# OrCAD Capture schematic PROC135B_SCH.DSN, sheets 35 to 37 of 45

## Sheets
35 35. USB1 TYPE-A: size C; title: SOC USB INTERFACE, USB1 TYPE A CONNECTOR, VBUS DIVIDER & POWER SWITCH
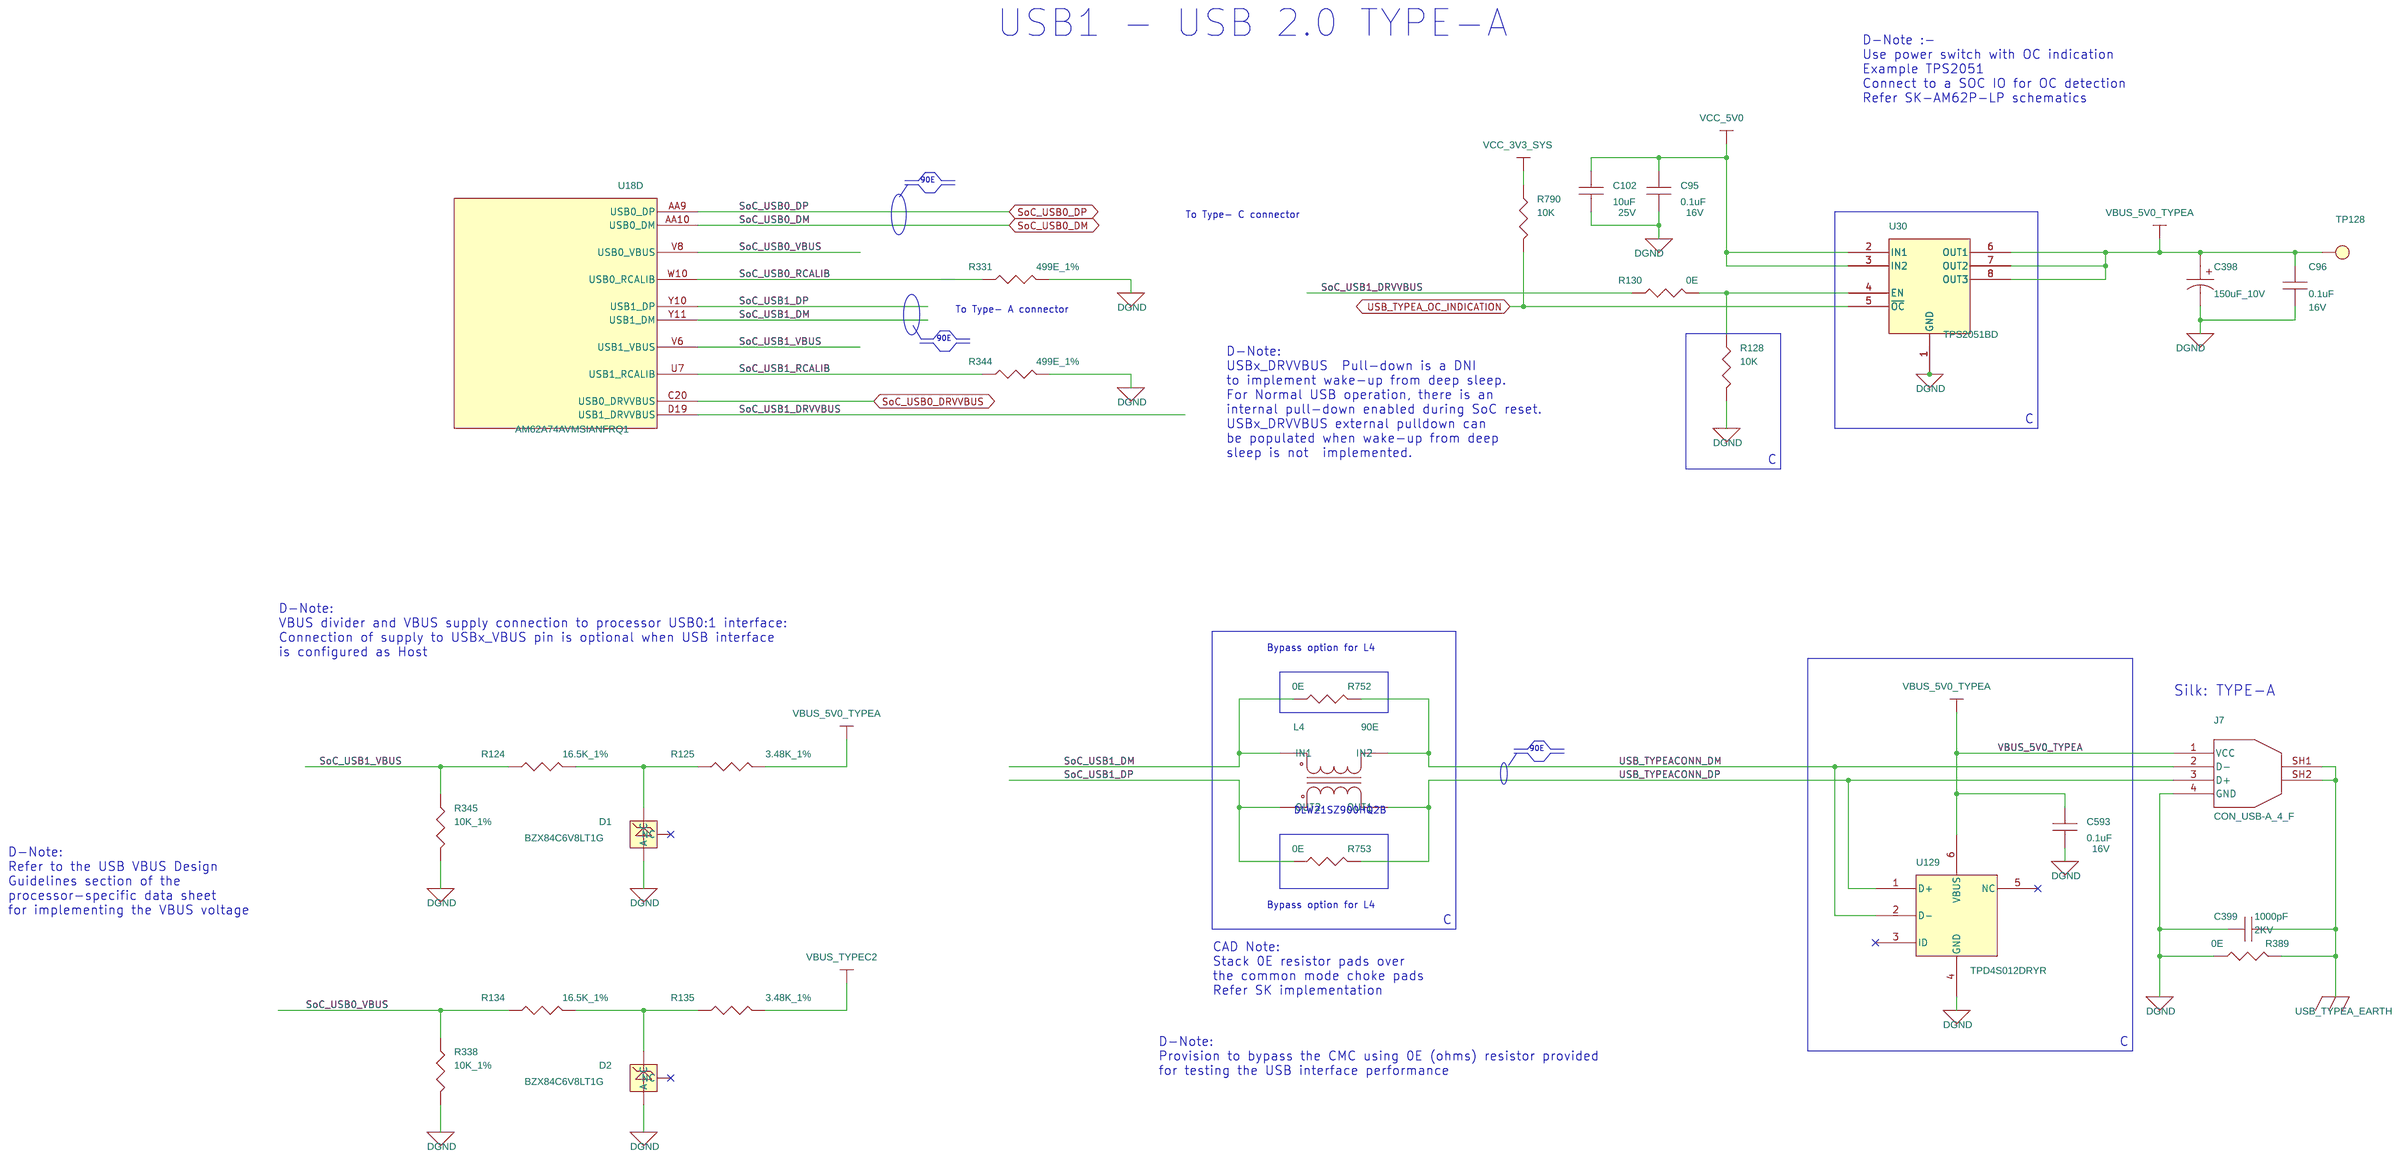
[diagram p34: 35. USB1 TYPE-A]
36 36. USB0 TYPE-C DRP & TEST LED: size C; title: USB0 TYPE-C DRP & USER TEST LEDS
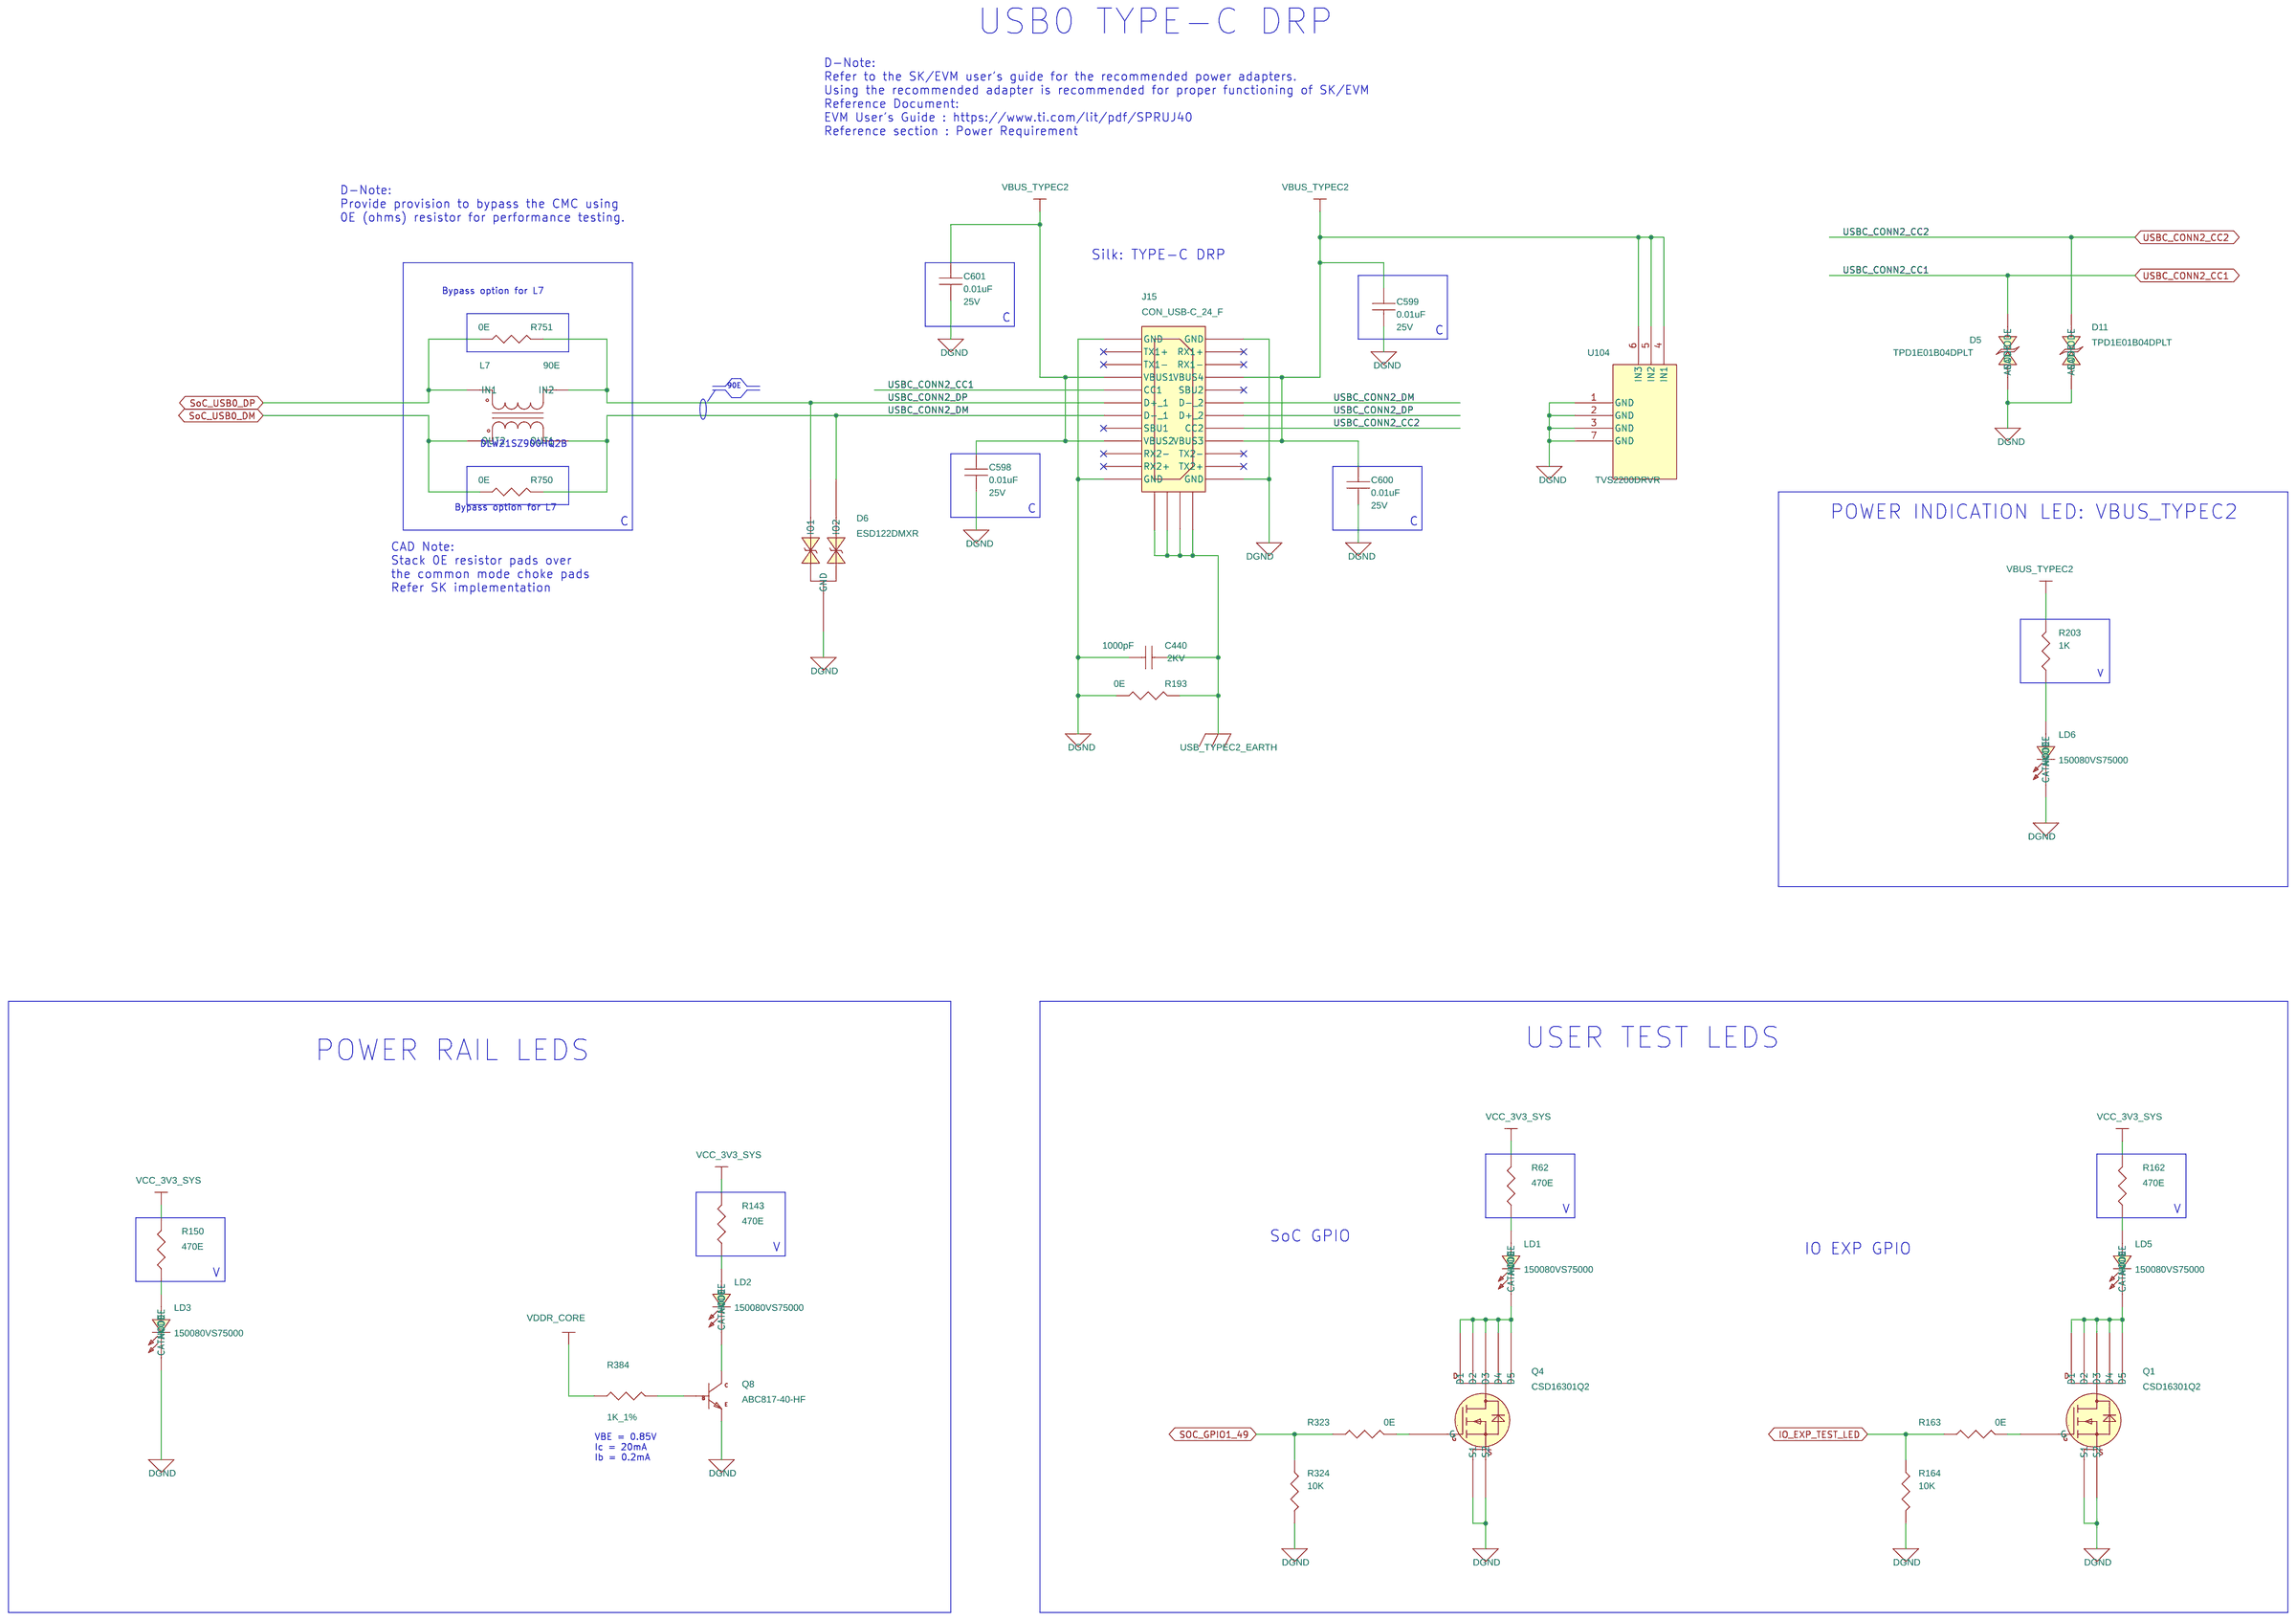
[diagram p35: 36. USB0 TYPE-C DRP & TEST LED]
37 37. SoC UART1 FET SWITCH & BUFF: size C; title: SoC UART1 FET SWITCH & BUFFER
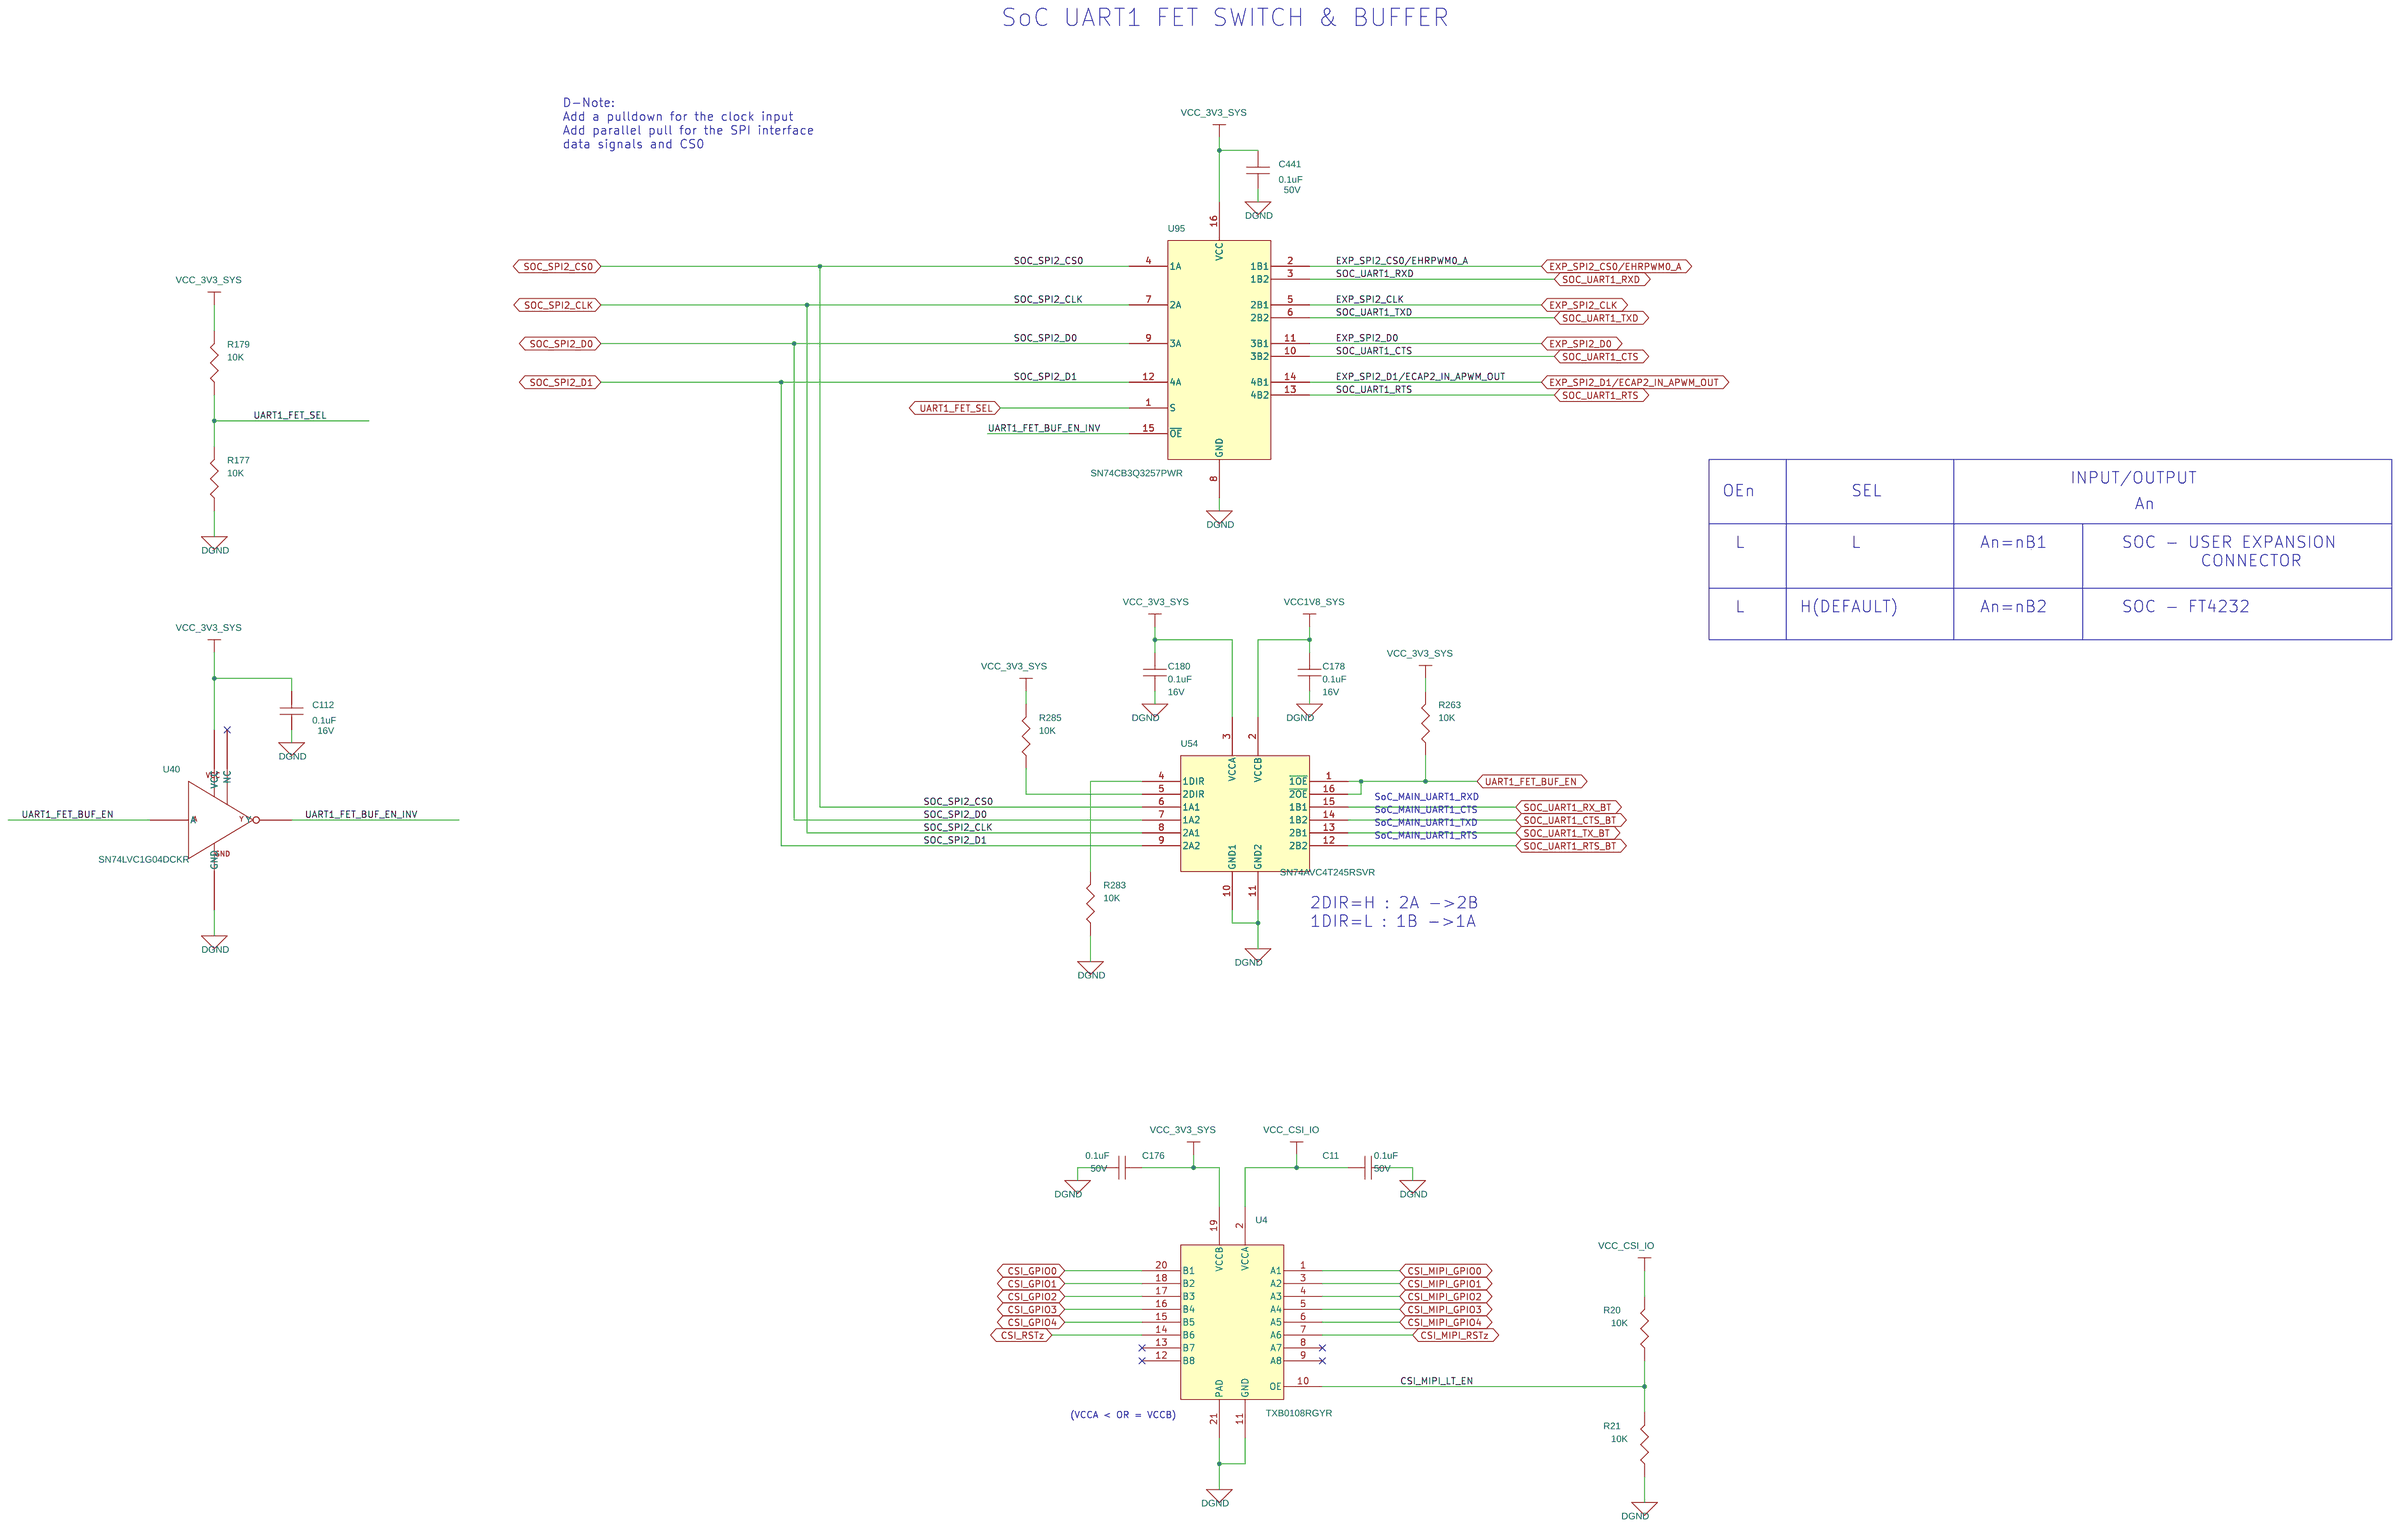
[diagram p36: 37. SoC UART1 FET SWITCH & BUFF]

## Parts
sheet 34. MCU HEADER
U18  AM62A74AVMSIANFRQ1  [FBGA484_31-49_710X710_2-7]  (sections A,B,C,D,E,F,G,H,I,J,K,L,M,N,O,P,Q)
sheet 35. USB1 TYPE-A
C95  0.1uF  [CAP0201_0-5]
C96  0.1uF  [CAP0201_0-5]
C102  10uF  [CAP0603_1]
C398  150uF_10V  [CAPT7343D_3-25]
C399  1000pF  [CAP1206_1-75]
C593  0.1uF  [CAP0201_0-5]
D1  BZX84C6V8LT1G  [SOT23-123_1-2]
D2  BZX84C6V8LT1G  [SOT23-123_1-2]
J7  CON_USB-A_4_F  [CON_USBA4_629104151_S_R_S_7-4]
L4  90E  [IND4_DLW21H_90X60_SMD_1-4]
R124  16.5K_1%  [RES0402_0-5]
R125  3.48K_1%  [RES0201_0-5]
R128  10K  [RES0201_0-5]
R130  0E  [RES0201_0-5]
R134  16.5K_1%  [RES0402_0-5]
R135  3.48K_1%  [RES0201_0-5]
R331  499E_1%  [RES0402_0-5]
R338  10K_1%  [RES0201_0-5]
R344  499E_1%  [RES0402_0-5]
R345  10K_1%  [RES0201_0-5]
R389  0E  [RES0603_0-75]
R752  0E  [RES0402_0-5]
R753  0E  [RES0402_0-5]
R790  10K  [RES0201_0-5]
TP128  TP20_SMD  [TP20_SMD]
U30  TPS2051BD  [SOIC8_1-8]
U129  TPD4S012DRYR  [SON6_SN74LVC2G17_40X60_0-6]
sheet 36. USB0 TYPE-C DRP & TEST LED
C440  1000pF  [CAP1206_1-75]
C598  0.01uF  [CAP0201_0-5]
C599  0.01uF  [CAP0201_0-5]
C600  0.01uF  [CAP0201_0-5]
C601  0.01uF  [CAP0201_0-5]
D5  TPD1E01B04DPLT  [DIO_DFN0201_0-4]
D6  ESD122DMXR  [X2SON3_ESD122DMX_30X40_0-4]
D11  TPD1E01B04DPLT  [DIO_DFN0201_0-4]
J15  CON_USB-C_24_F  [CON_USBC24_2012670_S_R_S_3-9]
L7  90E  [IND4_DLW21H_90X60_SMD_1-4]
LD1  150080VS75000  [LED_150080VS75000_80X50_SMD_0-8]
LD2  150080VS75000  [LED_150080VS75000_80X50_SMD_0-8]
LD3  150080VS75000  [LED_150080VS75000_80X50_SMD_0-8]
LD5  150080VS75000  [LED_150080VS75000_80X50_SMD_0-8]
LD6  150080VS75000  [LED_150080VS75000_80X50_SMD_0-8]
Q1  CSD16301Q2  [WSON6_CSD13202Q2_80X80_0-8]
Q4  CSD16301Q2  [WSON6_CSD13202Q2_80X80_0-8]
Q8  ABC817-40-HF  [SOT23-123_1-2]
R62  470E  [RES0402_0-5]
R143  470E  [RES0402_0-5]
R150  470E  [RES0402_0-5]
R162  470E  [RES0402_0-5]
R163  0E  [RES0402_0-5]
R164  10K  [RES0201_0-5]
R193  0E  [RES0603_0-75]
R203  1K  [RES0402_0-5]
R323  0E  [RES0402_0-5]
R324  10K  [RES0201_0-5]
R384  1K_1%  [RES0402_0-5]
R750  0E  [RES0402_0-5]
R751  0E  [RES0402_0-5]
U104  TVS2200DRVR  [SON6_25-59_85X85_0-8]
sheet 37. SoC UART1 FET SWITCH & BUFF
C11  0.1uF  [CAP0402_0-75]
C112  0.1uF  [CAP0201_0-5]
C176  0.1uF  [CAP0402_0-75]
C178  0.1uF  [CAP0201_0-5]
C180  0.1uF  [CAP0201_0-5]
C441  0.1uF  [CAP0402_0-75]
R20  10K  [RES0201_0-5]
R21  10K  [RES0201_0-5]
R177  10K  [RES0201_0-5]
R179  10K  [RES0201_0-5]
R263  10K  [RES0201_0-5]
R283  10K  [RES0201_0-5]
R285  10K  [RES0201_0-5]
U4  TXB0108RGYR  [QFN20_19-68_185X145_1]
U40  SN74LVC1G04DCKR  [SC70-5]
U54  SN74AVC4T245RSVR  [UQFN16_TMUX1574_70X100_0-6]
U95  SN74CB3Q3257PWR  [TSSOP16_25-59_205X180]

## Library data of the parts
U18 = AM62A-EVM_SOC_FCBGA484: IC AM62A SK EVM SoC MICROPROCESSOR FCBGA484; Chkd/date: PRADEEP/120225; Crtd /date: SHANKARI/120225; Custom_Duty: 15%; Customs_HS_Code: 85369090; Distributor_name: NA; Distributor_part_number: NA; Footprint Path: Y:\MIS_DATABASE\Library\ALTIUM_TOOL\PCB_FOOTPRINTS\Altium_Footprint_Lib.PcbLib; Height: 2.65MM; Library Path: Y:\MIS_DATABASE\Library\ALTIUM_TOOL\SCHEMATICS_PARTS\MS_MICROPROCESSOR_Library.schlib; Library Ref: AM62A-EVM_SoC_FCBGA484; Mfr_name: TEXAS INSTRUMENTS; Mistral Part No: 141225020003-R; Package: FCBGA484; Part_type: ICS\DIGITAL\MICROPROCESSOR; Project: AM62A_SK_EVM; RoHS: NA; Temperature: NA; Tolerance: NA; Voltage: NA; Wattage: NA; Weight: NA; Datasheet: Y:\MIS_DATABASE\DATASHEETS\ICS\DIGITAL\MICROCONTROLLER\AM62A_SK_EVM.PDF
C95 C96 C593 = CAP: CAP CERAMIC 0.1uF 16V 10% X5R 0201; Chkd/date: PRADEEP/130623; Crtd /date: PRADEEP/130623; Custom_Duty: 15%; Customs_HS_Code: 85322990; Distributor_name: NA; Distributor_part_number: NA; Footprint Path: Y:\MIS_DATABASE\Library\ALTIUM_TOOL\PCB_FOOTPRINTS\Altium_Footprint_Lib.PcbLib; Height: 0.33MM; Library Path: Y:\MIS_DATABASE\Library\ALTIUM_TOOL\SCHEMATICS_PARTS\MS_DISCRETE_Library.schlib; Mfr_name: MURATA; Mfr_part_number: GRT033R61C104KE01; Mistral Part No: 120022060019-R; Package: 0201; Part_type: CAPACITORS\CERAMIC; Project: AM62P_SK; RoHS: RoHS; Temperature: -55°C+85°C; Tolerance: 10%; Voltage: 16V; Wattage: NA; Weight: 0.33mg; Datasheet: Y:\MIS_DATABASE\DATASHEETS\CAPACITORS\GRT033R61C104KE01XX.PDF
C102 = CAP: CAP CERAMIC 10uF 25V 20% X5R AUTO 0603; Chkd/date: PRADEEP/130623; Crtd /date: PRADEEP/130623; Custom_Duty: 15%; Customs_HS_Code: 85322990; Distributor_name: NA; Distributor_part_number: NA; Footprint Path: Y:\MIS_DATABASE\Library\ALTIUM_TOOL\PCB_FOOTPRINTS\Altium_Footprint_Lib.PcbLib; Height: 1.00MM; Library Path: Y:\MIS_DATABASE\Library\ALTIUM_TOOL\SCHEMATICS_PARTS\MS_DISCRETE_Library.schlib; Mfr_name: MURATA; Mfr_part_number: GRT188R61E106ME13; Mistral Part No: 120022060023-R; Package: 0603; Part_type: CAPACITORS\CERAMIC; Project: AM62P_SK; RoHS: RoHS; Temperature: -55°C+85°C; Tolerance: 20%; Voltage: 25V; Wattage: NA; Weight: 2mg; Datasheet: Y:\MIS_DATABASE\DATASHEETS\CAPACITORS\GRT188R61E106ME13.PDF
C398 = CAP_POL: CAP TANTALUM 150uF 10V 10% ESR 600mE D7343; Chkd/date: ALVY/200921; Crtd /date: MANIRAJA/200921; Custom_Duty: 15%; Customs_HS_Code: 85322990; Distributor_name: DIGIKEY; Distributor_part_number: 718-1960-1-ND; Footprint Path: Y:\MIS_DATABASE\Library\ALTIUM_TOOL\PCB_FOOTPRINTS\Altium_Footprint_Lib.PcbLib; Height: 3.10MM; Library Path: Y:\MIS_DATABASE\Library\ALTIUM_TOOL\SCHEMATICS_PARTS\MS_DISCRETE_Library.schlib; Mfr_name: VISHAY; Mfr_part_number: 293D157X9010D2TE3; Mistral Part No: 120021090007-R; Package: D7343; Part_type: CAPACITORS\TANTALUM; Project: TI_AM62x SKEVM_BRD; RoHS: RoHS; Temperature: -55°C+125°C; Tolerance: 10%; Voltage: 10V; Wattage: NA; Weight: 400mg; Datasheet: Y:\MIS_DATABASE\DATASHEETS\CAPACITORS\293D_SER_MAR20.PDF
C399 C440 = CAP: CAP CERAMIC 1000pF 2KV 10% X7R 1206; Chkd/date: SHREESHAIL/291106; Crtd /date: MAZHAR/281106; Custom_Duty: 15%; Customs_HS_Code: 85322990; Distributor_name: DIGIKEY; Distributor_part_number: 478-2956-1-ND; Footprint Path: Y:\MIS_DATABASE\Library\ALTIUM_TOOL\PCB_FOOTPRINTS\Altium_Footprint_Lib.PcbLib; Height: 1.52MM; Library Path: Y:\MIS_DATABASE\Library\ALTIUM_TOOL\SCHEMATICS_PARTS\MS_DISCRETE_Library.schlib; Mfr_name: AVX CORPORATION; Mfr_part_number: 1206GC102KAT1A; Mistral Part No: 120015080006-R; Package: 1206; Part_type: CAPACITORS\CERAMIC; Project: ADR1B; RoHS: RoHS; Temperature: -55°C+125°C; Tolerance: 10%; Voltage: 2KV; Wattage: NA; Weight: 16.2mg; Datasheet: Y:\MIS_DATABASE\DATASHEETS\CAPACITORS\AVX_HV-MLC.PDF
D1 D2 = DIODE_ZENER_SOT23_13: DIODE ZENER 250mW 6.8V SOT23-123; Chkd/date: MANIRAJA/031017; Crtd /date: MANIRAJA/031017; Custom_Duty: 15%; Customs_HS_Code: 85412900; Distributor_name: DIGIKEY; Distributor_part_number: BZX84C6V8LT1GOSCT-ND; Height: 1.11MM; Mfr_name: ON SEMICONDUCTOR; Mistral Part No: 130017100002-R; Package: SOT23-123; Part_type: DIODE\ZENER; Project: TI_MAXIE_CPB; RoHS: RoHS; Temperature: -65°C+150°C; Tolerance: NA; Voltage: 6.8V; Wattage: NA; Weight: 8mg; Datasheet: Y:\MIS_DATABASE\DATASHEETS\DISCRETES\DIODES\BZX84XX.PDF
J7 = CON_USB-A_4_2SH: CON USB-A TYPE 4POS FEMALE RT SMD; Chkd/date: MANIRAJA/271017; Crtd /date: MANIRAJA/271017; Custom_Duty: 24%; Customs_HS_Code: 85369090; Distributor_name: DIGIKEY; Distributor_part_number: 732-5969-1-ND; Height: 7.35MM; Manufacturer: WURTH ELECTRONICS; Mfr_name: WURTH ELECTRONICS; Mfr_part_number: 629104151021; Mistral Part No: 150017100042-R; Package: SMD; Part_type: CONNECTOR\USB; Project: TI_SVB_MAXWELL_SPM; RoHS: RoHS; Temperature: -40°C+85°C; Tolerance: NA; Voltage: NA; Wattage: NA; Weight: NA; Datasheet: Y:\MIS_DATABASE\DATASHEETS\CONNECTORS\629104151021.PDF
L4 L7 = INDUCTOR_DLW31S: IND COMMON MODE CHOKE 90E 280mA SMD; Chkd/date: MANIRAJA/270619; Crtd /date: MANIRAJA/270619; Custom_Duty: 24%; Customs_HS_Code: 85437099; Distributor_name: NA; Distributor_part_number: NA; Footprint Path: Y:\MIS_DATABASE\Library\ALTIUM_TOOL\PCB_FOOTPRINTS\Altium_Footprint_Lib.PcbLib; Height: 1.40MM; Library Path: Y:\MIS_DATABASE\Library\ALTIUM_TOOL\SCHEMATICS_PARTS\MS_DISCRETE_Library.schlib; Mfr_name: MURATA; Mfr_part_number: DLW21SZ900HQ2B; Mistral Part No: 130019060035-R; Package: SMD; Part_type: INDUCTOR; Project: TI_J7ES_CP; RoHS: RoHS; Temperature: -40°C+105°C; Tolerance: NA; Voltage: NA; Wattage: NA; Weight: 11mg; Datasheet: Y:\MIS_DATABASE\DATASHEETS\DISCRETES\INDUCTORS\DLW21SZ900HQ2B.PDF
R124 R134 = RESISTOR: RES 16.5K 1/16W 1% 0402; Chkd/date: ALVY/091220; Crtd /date: MANIRAJA/091220; Custom_Duty: 15%; Customs_HS_Code: 85332119; Distributor_name: DIGIKEY; Distributor_part_number: YAG3002CT-ND; Footprint Path: Y:\MIS_DATABASE\Library\ALTIUM_TOOL\PCB_FOOTPRINTS\Altium_Footprint_Lib.PcbLib; Height: 0.40MM; Library Path: Y:\MIS_DATABASE\Library\ALTIUM_TOOL\SCHEMATICS_PARTS\MS_DISCRETE_Library.schlib; Mfr_name: YAGEO AMERICA; Mfr_part_number: RC0402FR-0716K5L; Mistral Part No: 110020120011-R; Package: 0402; Part_type: RESISTORS\FIXED; Project: TI_AM243x LP EVM; RoHS: RoHS; Temperature: -55°C+155°C; Tolerance: 1%; Voltage: NA; Wattage: 1/16W; Weight: 0.65mg; Datasheet: Y:\MIS_DATABASE\DATASHEETS\RESISTORS\RCXXXXL-SER_MAR18.PDF
R125 R135 = RESISTOR: RES 3.48K 1/20W 1% 0201; Chkd/date: PRADEEP/281123; Crtd /date: TAMILARASU/071123; Custom_Duty: 15%; Customs_HS_Code: 85322990; Distributor_name: DIGIKEY; Distributor_part_number: P122951CT-ND; Footprint Path: Y:\MIS_DATABASE\Library\ALTIUM_TOOL\PCB_FOOTPRINTS\Altium_Footprint_Lib.PcbLib; Height: 0.26MM; Library Path: Y:\MIS_DATABASE\Library\ALTIUM_TOOL\SCHEMATICS_PARTS\MS_DISCRETE_Library.schlib; Mfr_name: PANASONIC-ECG; Mfr_part_number: ERJ-1GNF3481C; Mistral Part No: 110023110006-R; Package: 0201; Part_type: RESISTORS\FIXED; Project: AM62P SK; RoHS: RoHS; Temperature: -55°C+125°C; Tolerance: 0.01; Voltage: NA; Wattage: 1/20W; Weight: 0.15mg; Datasheet: Y:\MIS_DATABASE\DATASHEETS\RESISTORS\PAN-ERJSER_DEC22.PDF
R20 R21 R128 R164 R177 R179 R263 R283 R285 R324 R790 = RESISTOR: RES 10K 1/20W 5% 0201; Chkd/date: MANIRAJA/050517; Crtd /date: MANIRAJA/050517; Custom_Duty: 15%; Customs_HS_Code: 85332119; Distributor_name: DIGIKEY; Distributor_part_number: 311-10KNCT-ND; Footprint Path: Y:\MIS_DATABASE\Library\ALTIUM_TOOL\PCB_FOOTPRINTS\Altium_Footprint_Lib.PcbLib; Height: 0.26MM; Library Path: Y:\MIS_DATABASE\Library\ALTIUM_TOOL\SCHEMATICS_PARTS\MS_DISCRETE_Library.schlib; Mfr_name: YAGEO AMERICA; Mfr_part_number: RC0201JR-0710KL; Mistral Part No: 110010070051-R; Package: 0201; Part_type: RESISTORS\FIXED; Project: GOLDEN-I LITE; RoHS: RoHS; Temperature: -55°C+125°C; Tolerance: 5%; Voltage: NA; Wattage: 1/20W; Weight: 0.17mg; Datasheet: Y:\MIS_DATABASE\DATASHEETS\RESISTORS\RCXXXXL-SER_MAR18.PDF
R130 = RESISTOR: RES 0E 1/20W 5% 0201; Chkd/date: NAVEED/301214; Crtd /date: MUDDU/120710; Custom_Duty: 15%; Customs_HS_Code: 85332119; Distributor_name: DIGIKEY; Distributor_part_number: 311-0.0NCT-ND; Footprint Path: Y:\MIS_DATABASE\Library\ALTIUM_TOOL\PCB_FOOTPRINTS\Altium_Footprint_Lib.PcbLib; Height: 0.26MM; Library Path: Y:\MIS_DATABASE\Library\ALTIUM_TOOL\SCHEMATICS_PARTS\MS_DISCRETE_Library.schlib; Mfr_name: YAGEO AMERICA; Mfr_part_number: RC0201JR-070RL; Mistral Part No: 110010070067-R; Package: 0201; Part_type: RESISTORS\FIXED; Project: PB_BUGBASE; RoHS: RoHS; Temperature: -55°C+125°C; Tolerance: 5%; Voltage: NA; Wattage: 1/20W; Weight: 0.17mg; Datasheet: Y:\MIS_DATABASE\DATASHEETS\RESISTORS\RCXXXXL-SER_MAR18.PDF
R331 R344 = RESISTOR: RES 499E 1/16W 1% 0402; Chkd/date: MANIRAJA/051020; Crtd /date: ALVY/051020; Custom_Duty: 15%; Customs_HS_Code: 85332119; Distributor_name: DIGIKEY; Distributor_part_number: 311-499LRCT-ND; Footprint Path: Y:\MIS_DATABASE\Library\ALTIUM_TOOL\PCB_FOOTPRINTS\Altium_Footprint_Lib.PcbLib; Height: 0.40MM; Library Path: Y:\MIS_DATABASE\Library\ALTIUM_TOOL\SCHEMATICS_PARTS\MS_DISCRETE_Library.schlib; Mfr_name: YAGEO AMERICA; Mfr_part_number: RC0402FR-07499RL; Mistral Part No: 110020080006-R; Package: 0402; Part_type: RESISTORS\FIXED; Project: AM64XX_EVM; RoHS: RoHS; Temperature: -55°C+155°C; Tolerance: 1%; Voltage: NA; Wattage: 1/16W; Weight: 0.65mg; Datasheet: Y:\MIS_DATABASE\DATASHEETS\RESISTORS\RCXXXXL-SER_MAR18.PDF
R338 R345 = RESISTOR: RES 10K 1/20W 1% 0201; Chkd/date: VASANTHA/270117; Crtd /date: MANIRAJA/270117; Custom_Duty: 15%; Customs_HS_Code: 85332119; Distributor_name: DIGIKEY; Distributor_part_number: 311-10.0KMCT-ND; Footprint Path: Y:\MIS_DATABASE\Library\ALTIUM_TOOL\PCB_FOOTPRINTS\Altium_Footprint_Lib.PcbLib; Height: 0.26MM; Library Path: Y:\MIS_DATABASE\Library\ALTIUM_TOOL\SCHEMATICS_PARTS\MS_DISCRETE_Library.schlib; Mfr_name: YAGEO AMERICA; Mfr_part_number: RC0201FR-0710KL; Mistral Part No: 110011040018-R; Package: 0201; Part_type: RESISTORS\FIXED; Project: GOLDEN-I LITE; RoHS: RoHS; Temperature: -55°C+125°C; Tolerance: 1%; Voltage: NA; Wattage: 1/20W; Weight: 0.17mg; Datasheet: Y:\MIS_DATABASE\DATASHEETS\RESISTORS\RCXXXXL-SER_MAR18.PDF
R193 R389 = RESISTOR: RES 0E 1/10W 5% 0603; Chkd/date: MANIRAJA/051217; Crtd /date: BAVISH/180211; Custom_Duty: 15%; Customs_HS_Code: 85332119; Distributor_name: DIGIKEY; Distributor_part_number: 311-0.0GRCT-ND; Footprint Path: Y:\MIS_DATABASE\Library\ALTIUM_TOOL\PCB_FOOTPRINTS\Altium_Footprint_Lib.PcbLib; Height: 0.55MM; Library Path: Y:\MIS_DATABASE\Library\ALTIUM_TOOL\SCHEMATICS_PARTS\MS_DISCRETE_Library.schlib; Manufacturer: YAGEO AMERICA; Mfr_name: PANASONIC-ECG; Mfr_part_number: RC0603JR-070RL; Mistral Part No: 110011020013-R; Package: 0603; Part_type: RESISTORS\FIXED; Project: KENNEL; RoHS: RoHS; Temperature: -55°C+155°C; Tolerance: 5%; Voltage: NA; Wattage: 1/10W; Weight: 2mg; Datasheet: Y:\MIS_DATABASE\DATASHEETS\RESISTORS\RCXXXXL-SER_MAR18.PDF
R163 R323 R750-R753 = RESISTOR: RES 0E 1/16W JUMPER 0402; Chkd/date: VASANTHA/201216; Crtd /date: MUDDU/190810; Custom_Duty: 15%; Customs_HS_Code: 85332119; Distributor_name: DIGIKEY; Distributor_part_number: 541-0.0JCT-ND; Footprint Path: Y:\MIS_DATABASE\Library\ALTIUM_TOOL\PCB_FOOTPRINTS\Altium_Footprint_Lib.PcbLib; Height: 0.40MM; Library Path: Y:\MIS_DATABASE\Library\ALTIUM_TOOL\SCHEMATICS_PARTS\MS_DISCRETE_Library.schlib; Mfr_name: VISHAY; Mfr_part_number: CRCW04020000Z0ED; Mistral Part No: 110010080019-R; Package: 0402; Part_type: RESISTORS\FIXED; Project: PB_BUGBASE; RoHS: RoHS; Temperature: -55°C+155°C; Tolerance: NA; Voltage: NA; Wattage: 1/16W; Weight: 0.65mg; Datasheet: Y:\MIS_DATABASE\DATASHEETS\RESISTORS\CRCW0603.PDF
TP128 = TESTPOINT: TESTPOINT CIR 20 SMD; Chkd/date: SHREESHAIL/171006; Crtd /date: MAZHAR/171006; Custom_Duty: NA; Customs_HS_Code: NA; Distributor_name: NA; Distributor_part_number: NA; Footprint Path: Y:\MIS_DATABASE\Library\ALTIUM_TOOL\PCB_FOOTPRINTS\Altium_Footprint_Lib.PcbLib; Height: NA; Library Path: Y:\MIS_DATABASE\Library\ALTIUM_TOOL\SCHEMATICS_PARTS\MS_DISCRETE_Library.schlib; MECHANICAL 3D STEP FILE: NA; Mfr_name: LOCAL; Mistral Part No: NA; Package: SMD; Project: BT MODULE_CSRBC04; RoHS: NA; Temperature: NA; Tolerance: NA; Voltage: NA; Wattage: NA; Weight: NA; Datasheet: NA
U30 = TPS2051BD_SOIC8: IC POWER DISTRIBUTION SWITCH SOIC8; Chkd/date: NAVEED/150714; Crtd /date: VASANTHA/190614; Custom_Duty: 15%; Customs_HS_Code: 85423100; Distributor_name: DIGIKEY; Distributor_part_number: 296-26911-5-ND; Footprint Path: Y:\MIS_DATABASE\Library\ALTIUM_TOOL\PCB_FOOTPRINTS\Altium_Footprint_Lib.PcbLib; Height: 1.75MM; Library Path: Y:\MIS_DATABASE\Library\ALTIUM_TOOL\SCHEMATICS_PARTS\MS_MISCPOWER_Library.schlib; Mfr_name: TEXAS INSTRUMENTS; Mistral Part No: 142014060011-R; Package: SOIC8; Part_type: ICS\POWER; Project: AEGIS_POM; RoHS: RoHS; Temperature: -40°C+125°C; Tolerance: NA; Voltage: NA; Wattage: NA; Weight: 72.6mg; Datasheet: Y:\MIS_DATABASE\DATASHEETS\MISC\REGULATORS\TPS2051BDBVR.PDF
U129 = TPD4S012DRY_SON6: IC 4CH ESD SOLUTION FOR USB-HS/USB OTG/USB CHARGER INTERFACE SON6; Chkd/date: MANIRAJA/040719; Crtd /date: BAVISH/190811; Custom_Duty: 15%; Customs_HS_Code: 85423100; Distributor_name: DIGIKEY; Distributor_part_number: 296-24244-1-ND; Footprint Path: Y:\MIS_DATABASE\Library\ALTIUM_TOOL\PCB_FOOTPRINTS\Altium_Footprint_Lib.PcbLib; Height: 0.60MM; Library Path: Y:\MIS_DATABASE\Library\ALTIUM_TOOL\SCHEMATICS_PARTS\MS_MISCINTERFACE_Library.schlib; Mfr_name: TEXAS INSTRUMENTS; Mistral Part No: 141011080022-R; Package: SON6; Part_type: ICS\INTERFACE; Project: ACRO_DM3730; RoHS: RoHS; Temperature: -40°C+85°C; Tolerance: NA; Voltage: NA; Wattage: NA; Weight: 3.2mg; Datasheet: Y:\MIS_DATABASE\DATASHEETS\ICS\INTERFACE\TPD4S012DRYR.PDF
C598-C601 = CAP: CAP CERAMIC 0.01uF 25V 10% X5R AUTO 0201; Chkd/date: MANIRAJA/311221; Crtd /date: ALVY/301221; Custom_Duty: 15%; Customs_HS_Code: 85322990; Distributor_name: MOUSER; Distributor_part_number: 81-GRT033R61E103KE1D; Footprint Path: Y:\MIS_DATABASE\Library\ALTIUM_TOOL\PCB_FOOTPRINTS\Altium_Footprint_Lib.PcbLib; Height: 0.33MM; Library Path: Y:\MIS_DATABASE\Library\ALTIUM_TOOL\SCHEMATICS_PARTS\MS_DISCRETE_Library.schlib; Mfr_name: MURATA; Mfr_part_number: GRT033R61E103KE01D; Mistral Part No: 120021120019-R; Package: 0201; Part_type: CAPACITORS\CERAMIC; Project: AM62Q_SKEVM_BRD; RoHS: RoHS; Temperature: -55°C+85°C; Tolerance: 10%; Voltage: 25V; Wattage: NA; Weight: 0.33mg; Datasheet: Y:\MIS_DATABASE\DATASHEETS\CAPACITORS\GRT033R61E103KE01.PDF
D5 D11 = DIODE_TVS_DUAL: DIODE 1CH ESD PROTECTION FOR USB TYPE-C AND THUNDERBOLT3 X2SON2; Chkd/date: MANIRAJA/230920; Crtd /date: ALVY/230920; Custom_Duty: 15%; Customs_HS_Code: 85412900; Distributor_name: DIGIKEY; Distributor_part_number: 296-44484-1-ND; Footprint Path: Y:\MIS_DATABASE\Library\ALTIUM_TOOL\PCB_FOOTPRINTS\Altium_Footprint_Lib.PcbLib; Height: 0.32MM; Library Path: Y:\MIS_DATABASE\Library\ALTIUM_TOOL\SCHEMATICS_PARTS\MS_DISCRETE_Library.schlib; Mfr_name: TEXAS INSTRUMENTS; Mistral Part No: 130020090037-R; Package: X2SON2; Part_type: DIODE\TVS; Project: AM64X_SKEVM; RoHS: RoHS; Temperature: -40°C+125°C; Tolerance: NA; Voltage: NA; Wattage: NA; Weight: 0.2mg; Datasheet: Y:\MIS_DATABASE\DATASHEETS\DISCRETES\DIODES\TPD1E01B04.PDF
D6 = DIODE_ESD122DMXR: DIODE 2-CH ESD PROTECTION FOR USB TYPE-C AND HDMI 2.0 X2SON-3; Chkd/date: MANIRAJA/140817; Crtd /date: MANIRAJA/140817; Custom_Duty: 15%; Customs_HS_Code: 85412900; Distributor_name: DIGIKEY; Distributor_part_number: ESD122DMXR-ND; Height: 0.40MM; Mfr_name: TEXAS INSTRUMENTS; Mistral Part No: 130017080015-R; Package: X2SON-3; Part_type: DIODE\TVS; Project: TI_SVB_CONTROLLER CARD; RoHS: RoHS; Temperature: -40°C+125°C; Tolerance: NA; Voltage: NA; Wattage: NA; Weight: NA; Datasheet: Y:\MIS_DATABASE\DATASHEETS\DISCRETES\DIODES\ESD122XX.PDF
J15 = CON_USB-C_24_1240183621: CON USB-C TYPE 24POS FEMALE RT SMD; Chkd/date: MANIRAJA/050618; Crtd /date: ALVY/040618; Custom_Duty: 24%; Customs_HS_Code: 85369090; Distributor_name: DIGIKEY; Distributor_part_number: WM17992CT-ND; Footprint Path: Y:\MIS_DATABASE\Library\ALTIUM_TOOL\PCB_FOOTPRINTS\Altium_Footprint_Lib.PcbLib; Height: 3.86MM; Library Path: Y:\MIS_DATABASE\Library\ALTIUM_TOOL\SCHEMATICS_PARTS\MS_CONNECTOR_Library.schlib; Mfr_name: MOLEX; Mfr_part_number: 2012670005; Mistral Part No: 150018060002-R; Package: SMD; Part_type: CONNECTOR\USB; Project: TI_J7SVB_USB_ADD-ON-CARD; RoHS: RoHS; Temperature: -40°C+105°C; Tolerance: NA; Voltage: NA; Wattage: NA; Weight: 0.686g; Datasheet: Y:\MIS_DATABASE\DATASHEETS\CONNECTORS\2012670X.PDF
LD1-LD3 LD5 LD6 = DIODE_LED: DIODE LED BRIGHT GREEN SMD; Chkd/date: MANIRAJA/180820; Crtd /date: ALVY/180820; Custom_Duty: 24%; Customs_HS_Code: 85439000; Distributor_name: DIGIKEY; Distributor_part_number: 732-4986-1-ND; Footprint Path: Y:\MIS_DATABASE\Library\ALTIUM_TOOL\PCB_FOOTPRINTS\Altium_Footprint_Lib.PcbLib; Height: 0.80MM; Library Path: Y:\MIS_DATABASE\Library\ALTIUM_TOOL\SCHEMATICS_PARTS\MS_OPTO_Library.schlib; Mfr_name: WURTH ELECTRONICS; Mistral Part No: 130020080012-R; Package: SMD; Part_type: OPTO\LED; Project: AM64x_EVM_BRD; RoHS: RoHS; Temperature: -40°C+85°C; Tolerance: NA; Voltage: NA; Wattage: NA; Weight: 10mg; Datasheet: Y:\MIS_DATABASE\DATASHEETS\DISCRETES\LEDS\150080VS75000.PDF
Q1 Q4 = MOSFET_CSD17313Q2: IC MOSFET N-CHANNEL NEXFET 25V WSON6; Chkd/date: ALVY/071220; Crtd /date: MANIRAJA/071220; Custom_Duty: 15%; Customs_HS_Code: 85423100; Distributor_name: DIGIKEY; Distributor_part_number: 296-25260-1-ND; Footprint Path: Y:\MIS_DATABASE\Library\ALTIUM_TOOL\PCB_FOOTPRINTS\Altium_Footprint_Lib.PcbLib; Height: 0.80MM; Library Path: Y:\MIS_DATABASE\Library\ALTIUM_TOOL\SCHEMATICS_PARTS\MS_MOSFET_Library.schlib; Manufacturer: TEXAS INSTRUMENTS; Mfr_name: TEXAS INSTRUMENTS; Mistral Part No: 142020120008-R; Package: WSON6; Part_type: ICS\POWER\MOSFET; Project: TI_AM243x LP EVM; RoHS: RoHS; Temperature: -55°C+150°C; Tolerance: NA; Voltage: NA; Wattage: NA; Weight: 8.7mg; Datasheet: Y:\MIS_DATABASE\DATASHEETS\ICS\POWER\CSD16301Q2.PDF
Q8 = NPN_123_SOT23-3: TRANSISTOR 45V 500mA NPN GENERAL PURPOSE SOT23-3; Chkd/date: PRAVEEN/260822; Crtd /date: PRAVEEN/260822; Custom_Duty: 15%; Customs_HS_Code: 85423100; Distributor_name: MOUSER; Distributor_part_number: 750-ABC817-40-HF; Footprint Path: Y:\MIS_DATABASE\Library\ALTIUM_TOOL\PCB_FOOTPRINTS\Altium_Footprint_Lib.PcbLib; Height: 1.20MM; Library Path: Y:\MIS_DATABASE\Library\ALTIUM_TOOL\SCHEMATICS_PARTS\MS_MOSFET_Library.schlib; Mfr_name: COMCHIP; Mistral Part No: 142022080040-R; Package: TO-252-3; Part_type: TRANSISTOR\BJT; Project: MS_TI_TMDS64SKEVM; RoHS: RoHS; Temperature: -55°C+150°C; Tolerance: NA; Voltage: 45V; Wattage: NA; Weight: NA; Datasheet: Y:\MIS_DATABASE\DATASHEETS\DISCRETES\TRANSISTORS_FETS\ABC817-40-HF.PDF
R62 R143 R150 R162 = RESISTOR: RES 470E 1/10W 5% 0402; Chkd/date: SHREESHAIL/24050; Crtd /date: MAZHAR/260706; Custom_Duty: 15%; Customs_HS_Code: 85332119; Distributor_name: DIGIKEY; Distributor_part_number: P470JCT-ND; Footprint Path: Y:\MIS_DATABASE\Library\ALTIUM_TOOL\PCB_FOOTPRINTS\Altium_Footprint_Lib.PcbLib; Height: 0.40MM; Library Path: Y:\MIS_DATABASE\Library\ALTIUM_TOOL\SCHEMATICS_PARTS\MS_DISCRETE_Library.schlib; Mfr_name: PANASONIC-ECG; Mfr_part_number: ERJ-2GEJ471X; Mistral Part No: 110009030859-R; Package: 0402; Part_type: RESISTORS\FIXED; Project: POWERBOX; RoHS: RoHS; Temperature: -55°C+155°C; Tolerance: 5%; Voltage: NA; Wattage: 1/10W; Weight: 0.8mg; Datasheet: Y:\MIS_DATABASE\DATASHEETS\RESISTORS\PAN-ERJSER_NOV17.PDF
R203 = RESISTOR: RES 1K 1/10W 5% 0402; Chkd/date: VASANTHA/201216; Crtd /date: MAZHAR/230805; Custom_Duty: 15%; Customs_HS_Code: 85332119; Distributor_name: DIGIKEY; Distributor_part_number: P1.0KJCT-ND; Footprint Path: Y:\MIS_DATABASE\Library\ALTIUM_TOOL\PCB_FOOTPRINTS\Altium_Footprint_Lib.PcbLib; Height: 0.40MM; Library Path: Y:\MIS_DATABASE\Library\ALTIUM_TOOL\SCHEMATICS_PARTS\MS_DISCRETE_Library.schlib; Mfr_name: PANASONIC-ECG; Mfr_part_number: ERJ-2GEJ102X; Mistral Part No: 110009030400-R; Package: 0402; Part_type: RESISTORS\FIXED; Project: HSE; RoHS: RoHS; Temperature: -55°C+155°C; Tolerance: 5%; Voltage: NA; Wattage: 1/10W; Weight: 0.8mg; Datasheet: Y:\MIS_DATABASE\DATASHEETS\RESISTORS\PAN-ERJSER_NOV17.PDF
R384 = RESISTOR: RES 1K 1/10W 1% 0402; Chkd/date: VASANTHA/281216; Crtd /date: MAZHAR/150506; Custom_Duty: 15%; Customs_HS_Code: 85332119; Distributor_name: DIGIKEY; Distributor_part_number: P1.00KLCT-ND; Footprint Path: Y:\MIS_DATABASE\Library\ALTIUM_TOOL\PCB_FOOTPRINTS\Altium_Footprint_Lib.PcbLib; Height: 0.40MM; Library Path: Y:\MIS_DATABASE\Library\ALTIUM_TOOL\SCHEMATICS_PARTS\MS_DISCRETE_Library.schlib; Mfr_name: PANASONIC-ECG; Mfr_part_number: ERJ-2RKF1001X; Mistral Part No: 110009030411-R; Package: 0402; Part_type: RESISTORS\FIXED; Project: VOCERA; RoHS: RoHS; Temperature: -55°C+155°C; Tolerance: 1%; Voltage: NA; Wattage: 1/10W; Weight: 0.8mg; Datasheet: Y:\MIS_DATABASE\DATASHEETS\RESISTORS\PAN-ERJSER_NOV17.PDF
U104 = TVS2200_WSON6: IC 22V FLAT-CLAMP SURGE PROTECTION DEVICE WSON6; Chkd/date: MANIRAJA/011021; Crtd /date: ALVY/011021; Custom_Duty: 15%; Customs_HS_Code: 85423100; Distributor_name: DIGIKEY; Distributor_part_number: 296-52187-1-ND; Footprint Path: Y:\MIS_DATABASE\Library\ALTIUM_TOOL\PCB_FOOTPRINTS\Altium_Footprint_Lib.PcbLib; Height: 0.80MM; Library Path: Y:\MIS_DATABASE\Library\ALTIUM_TOOL\SCHEMATICS_PARTS\MS_MISCPOWER_Library.schlib; Mfr_name: TEXAS INSTRUMENTS; Mistral Part No: 142021100001-R; Package: WSON6; Part_type: ICS\POWER; Project: TI_AM62x SKEVM_BRD; RoHS: RoHS; Temperature: -40°C+125°C; Tolerance: NA; Voltage: NA; Wattage: NA; Weight: 12mg; Datasheet: Y:\MIS_DATABASE\DATASHEETS\ICS\POWER\TVS2200.PDF
C11 C176 C441 = CAP: CAP CERAMIC 0.1uF 50V 10% X7R AUTO 0402; Alt_Mfr_name: YAGEO AMERICA; Alt_Mfr_part_number: CC0402KRX5R8BB104; Chkd/date: MANIRAJA/250221; Crtd /date: ALVY/240221; Custom_Duty: 15%; Customs_HS_Code: 85322990; Distributor_name: MOUSER; Distributor_part_number: 81-GRT155R71H104KE1D; Footprint Path: Y:\MIS_DATABASE\Library\ALTIUM_TOOL\PCB_FOOTPRINTS\Altium_Footprint_Lib.PcbLib; Height: 0.55MM; Library Path: Y:\MIS_DATABASE\Library\ALTIUM_TOOL\SCHEMATICS_PARTS\MS_DISCRETE_Library.schlib; Mfr_name: MURATA; Mfr_part_number: GRT155R71H104KE01D; Mistral Part No: 120019030005-R; Package: 0402; Part_type: CAPACITORS\CERAMIC; Project: TI_DRA821 SK EVM BRD; RoHS: RoHS; Temperature: -55°C+125°C; Tolerance: 10%; Voltage: 50V; Wattage: NA; Weight: NA; Datasheet: Y:\MIS_DATABASE\DATASHEETS\CAPACITORS\GRT155R71H104KE01.PDF
C112 C178 C180 = CAP: CAP CERAMIC 0.1uF 16V 10% X5R 0201; Alt_Mfr_name: YAGEO AMERICA; Alt_Mfr_part_number: CC0402KRX5R8BB104; Chkd/date: PRADEEP/130623; Crtd /date: PRADEEP/130623; Custom_Duty: 15%; Customs_HS_Code: 85322990; Distributor_name: NA; Distributor_part_number: NA; Footprint Path: Y:\MIS_DATABASE\Library\ALTIUM_TOOL\PCB_FOOTPRINTS\Altium_Footprint_Lib.PcbLib; Height: 0.33MM; Library Path: Y:\MIS_DATABASE\Library\ALTIUM_TOOL\SCHEMATICS_PARTS\MS_DISCRETE_Library.schlib; Mfr_name: MURATA; Mfr_part_number: GRT033R61C104KE01; Mistral Part No: 120022060019-R; Package: 0201; Part_type: CAPACITORS\CERAMIC; Project: AM62P_SK; RoHS: RoHS; Temperature: -55°C+85°C; Tolerance: 10%; Voltage: 16V; Wattage: NA; Weight: 0.33mg; Datasheet: Y:\MIS_DATABASE\DATASHEETS\CAPACITORS\GRT033R61C104KE01XX.PDF
U4 = TXB0108RGYR_VQFN20: IC 8-BIT TRANSLATOR 15KV ESD VQFN20; Chkd/date: VASANTHA/221216; Crtd /date: MUDDU/190510; Custom_Duty: 15%; Customs_HS_Code: 85423100; Distributor_name: DIGIKEY; Distributor_part_number: 296-21528-1-ND; Height: 1.00MM; Mfr_name: TEXAS INSTRUMENTS; Mistral Part No: 141010050005-R; Package: VQFN20; Part_type: ICS\INTERFACE; Project: SHIVA; RoHS: Sb/ Br FREE; Temperature: -40°C+85°C; Tolerance: NA; Voltage: NA; Wattage: NA; Weight: 43mg; Datasheet: Y:\MIS_DATABASE\DATASHEETS\ICS\INTERFACE\TXB0108RGYR.PDF
U40 = SN74LVC1G04DCKR_SC70-5: IC SINGLE INVERTER GATE SC70-5; Chkd/date: SUHAS/221010; Crtd /date: USMAN/150709; Custom_Duty: 15%; Customs_HS_Code: 85423100; Distributor_name: DIGIKEY; Distributor_part_number: 296-11600-1-ND; Height: 1.10MM; Mfr_name: TEXAS INSTRUMENTS; Mistral Part No: 141009070007-R; Part_type: ICS\DIGITAL\GATES; Project: BUG_BASE-II; RoHS: Sb/ Br FREE; Temperature: -40°C+85°C; Datasheet: Y:\MIS_DATABASE\DATASHEETS\ICS\DIGITAL\GATES\SN74LVC1G04-1.PDF
U54 = SN74AVC4T245RSV_UQFN16: IC 2-BIT BUS TRANSCEIVER WITH CONFIGURABLE VOLTAGE TRANSLATION AND 3 STATE O/P UQFN16; Chkd/date: MANIRAJA/040520; Crtd /date: BAVISH/190411; Custom_Duty: 15%; Customs_HS_Code: 85423100; Distributor_name: DIGIKEY; Distributor_part_number: 296-24366-1-ND; Footprint Path: Y:\MIS_DATABASE\Library\ALTIUM_TOOL\PCB_FOOTPRINTS\Altium_Footprint_Lib.PcbLib; Height: 0.55MM; Library Path: Y:\MIS_DATABASE\Library\ALTIUM_TOOL\SCHEMATICS_PARTS\MS_BUSDRIVERTRANSCEIVER_Library.schlib; Mfr_name: TEXAS INSTRUMENTS; Mistral Part No: 141011040011-R; Package: UQFN16; Part_type: ICS\DIGITAL\BUSTRANSCEIVER; Project: HMC; RoHS: RoHS; Temperature: -40°C+85°C; Tolerance: NA; Voltage: NA; Wattage: NA; Weight: 41mg; Datasheet: Y:\MIS_DATABASE\DATASHEETS\ICS\DIGITAL\BUSTRANSCEIVER\SN74AVC4T245-SER.PDF
U95 = SN74CB3Q3257PWR_TSSOP16: IC 4BIT 1-OF-2 FET MULTIPLEXER/DEMULTIPLEXER TSSOP16; Chkd/date: SUHAS/251010; Crtd /date: USMAN/060109; Custom_Duty: 15%; Customs_HS_Code: 85423100; Distributor_name: DIGIKEY; Distributor_part_number: 296-19138-1-ND; Height: 1.20MM; Mfr_name: TEXAS INSTRUMENTS; Mistral Part No: 141009030117-R; Package: TSSOP16; Part_type: ICS\DIGITAL\COMBINATIONAL; Project: OMAP_EVM; RoHS: Sb/ Br FREE; Temperature: -40°C+85°C; Datasheet: Y:\MIS_DATABASE\DATASHEETS\ICS\DIGITAL\COMBINATIONAL\SN74CB3Q3257.PDF

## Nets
DGND: C11.1 C95.2 C96.2 C102.2 C112.1 C176.1 C178.1 C180.1 C398.2 C399.2 C440.2 C441.1 C593.2 C598.2 C599.2 C600.2 C601.2 D1.1(A) D2.1(A) D5.2(ANODE) D6.1(GND) D11.2(ANODE) J7.4(GND) J15.A1(GND) J15.A12(GND) J15.B1(GND) J15.B12(GND) LD3.1(CATHODE) LD6.1(CATHODE) Q1.4(S1) Q1.7(S2) Q4.4(S1) Q4.7(S2) Q8.2(EMITTER) R21.1 R128.2 R164.1 R177.1 R193.2 R283.1 R324.1 R331.2 R338.2 R344.2 R345.2 R389.2 U4.11(GND) U4.21(PAD) U30.1(GND) U40.3(GND) U54.10(GND1) U54.11(GND2) U95.8(GND) U104.1(GND) U104.2(GND) U104.3(GND) U104.7(GND) U129.4(GND) ; also on sheet 10 11 12 13 14 15 16 17 18 19 20 21 22 23 24 25 26 27 28 29 30 31 32 33 34 38 39 40 41 42 43 44
VBUS_5V0_TYPEA: C96.1 C398.1 C593.1 J7.1(VCC) R125.2 TP128.1(TP) U30.6(OUT1) U30.7(OUT2) U30.8(OUT3) U129.6(VBUS)
VBUS_TYPEC2: C598.1 C599.1 C600.1 C601.1 J15.A4(VBUS1) J15.A9(VBUS2) J15.B4(VBUS3) J15.B9(VBUS4) R135.2 R203.2 U104.4(IN1) U104.5(IN2) U104.6(IN3) ; also on sheet 10
VCC1V8_SYS: C178.2 U54.2(VCCB) ; also on sheet 13 18 19 21 34 39 40 42
VCC_3V3_SYS: C112.2 C176.2 C180.2 C441.2 R62.2 R143.2 R150.2 R162.2 R179.2 R263.2 R285.2 R790.1 U4.19(VCCB) U40.5(VCC) U54.3(VCCA) U95.16(VCC) ; also on sheet 10 11 13 14 18 19 20 22 23 24 26 27 29 30 31 33 34 38 39 40 41 42 43
VCC_5V0: C95.1 C102.1 U30.2(IN1) U30.3(IN2) ; also on sheet 10 11 15 33 38 41
VCC_CSI_IO: C11.2 R20.2 U4.2(VCCA) ; also on sheet 38
VDDR_CORE: R384.1 ; also on sheet 13 15 16
CSI_GPIO0: U4.20(B1) ; also on sheet 38 40
CSI_GPIO1: U4.18(B2) ; also on sheet 38 40
CSI_GPIO2: U4.17(B3) ; also on sheet 42
CSI_GPIO3: U4.16(B4) ; also on sheet 42
CSI_GPIO4: U4.15(B5) ; also on sheet 42
CSI_MIPI_GPIO0: U4.1(A1) ; also on sheet 38
CSI_MIPI_GPIO1: U4.3(A2) ; also on sheet 38
CSI_MIPI_GPIO2: U4.4(A3) ; also on sheet 38
CSI_MIPI_GPIO3: U4.5(A4) ; also on sheet 38
CSI_MIPI_GPIO4: U4.6(A5) ; also on sheet 38
CSI_MIPI_LT_EN: R20.1 R21.2 U4.10(OE)
CSI_MIPI_RSTz: U4.7(A6) ; also on sheet 38
CSI_RSTz: U4.14(B6) ; also on sheet 40
EXP_SPI2_CLK: U95.5(2B1) ; also on sheet 33
EXP_SPI2_CS0/EHRPWM0_A: U95.2(1B1) ; also on sheet 33
EXP_SPI2_D0: U95.11(3B1) ; also on sheet 33
EXP_SPI2_D1/ECAP2_IN_APWM_OUT: U95.14(4B1) ; also on sheet 33
IO_EXP_TEST_LED: R163.1 R164.2 ; also on sheet 40
SOC_GPIO1_49: R323.1 R324.2 ; also on sheet 19
SOC_SPI2_CLK: U54.8(2A1) U95.7(2A) ; also on sheet 33
SOC_SPI2_CS0: U54.6(1A1) U95.4(1A) ; also on sheet 33
SOC_SPI2_D0: U54.7(1A2) U95.9(3A) ; also on sheet 33
SOC_SPI2_D1: U54.9(2A2) U95.12(4A) ; also on sheet 33
SOC_UART1_CTS: U95.10(3B2) ; also on sheet 31
SOC_UART1_CTS_BT: U54.14(1B2) ; also on sheet 18
SOC_UART1_RTS: U95.13(4B2) ; also on sheet 31
SOC_UART1_RTS_BT: U54.12(2B2) ; also on sheet 18
SOC_UART1_RX_BT: U54.15(1B1) ; also on sheet 18
SOC_UART1_RXD: U95.3(1B2) ; also on sheet 31
SOC_UART1_TX_BT: U54.13(2B1) ; also on sheet 18
SOC_UART1_TXD: U95.6(2B2) ; also on sheet 31
SoC_USB0_DM: L7.4(OUT2) R750.2 U18.AA10(USB0_DM)
SoC_USB0_DP: L7.1(IN1) R751.2 U18.AA9(USB0_DP)
SoC_USB0_DRVVBUS: U18.C20(USB0_DRVVBUS) ; also on sheet 10
SoC_USB0_RCALIB: R331.1 U18.W10(USB0_RCALIB)
SoC_USB0_VBUS: R134.1 R338.1 U18.V8(USB0_VBUS)
SoC_USB1_DM: L4.1(IN1) R752.2 U18.Y11(USB1_DM)
SoC_USB1_DP: L4.4(OUT2) R753.2 U18.Y10(USB1_DP)
SoC_USB1_DRVVBUS: R130.1 U18.D19(USB1_DRVVBUS)
SoC_USB1_RCALIB: R344.1 U18.U7(USB1_RCALIB)
SoC_USB1_VBUS: R124.1 R345.1 U18.V6(USB1_VBUS)
UART1_FET_BUF_EN: R263.1 U40.2(A) U54.1(~{1OE}) U54.16(~{2OE}) ; also on sheet 40
UART1_FET_BUF_EN_INV: U40.4(Y) U95.15(~{OE})
UART1_FET_SEL: R177.2 R179.1 U95.1(S) ; also on sheet 40
USB_TYPEA_EARTH: C399.1 J7.SH1 J7.SH2 R389.1
USB_TYPEA_OC_INDICATION: R790.2 U30.5(~{OC}) ; also on sheet 40
USB_TYPEACONN_DM: J7.2(D-) L4.2(IN2) R752.1 U129.2(D-)
USB_TYPEACONN_DP: J7.3(D+) L4.3(OUT1) R753.1 U129.1(D+)
USB_TYPEC2_EARTH: C440.1 J15.SH1 J15.SH2 J15.SH3 J15.SH4 R193.1
USBC_CONN2_CC1: D5.1(CATHODE) J15.A5(CC1) ; also on sheet 10
USBC_CONN2_CC2: D11.1(CATHODE) J15.B5(CC2) ; also on sheet 10
USBC_CONN2_DM: D6.3(IO2) J15.A7(D-_1) J15.B7(D-_2) L7.3(OUT1) R750.1
USBC_CONN2_DP: D6.2(IO1) J15.A6(D+_1) J15.B6(D+_2) L7.2(IN2) R751.1
N17031262: LD6.2(ANODE) R203.1
N17726648: D2.3(C) R134.2 R135.1
N20199452: D1.3(C) R124.2 R125.1
N20933818: R283.2 U54.4(1DIR)
N20933822: R285.1 U54.5(2DIR)
N22685157: LD2.1(CATHODE) Q8.3(COLLECTOR)
N22685161: LD2.2(ANODE) R143.1
N22685196: Q8.1(BASE) R384.2
N22685214: LD3.2(ANODE) R150.1
N22685527: LD5.1(CATHODE) Q1.1(D1) Q1.2(D2) Q1.5(D3) Q1.6(D4) Q1.8(D5)
N22685551: LD1.1(CATHODE) Q4.1(D1) Q4.2(D2) Q4.5(D3) Q4.6(D4) Q4.8(D5)
N22685595: Q4.3(G) R323.2
N22685622: LD1.2(ANODE) R62.1
N22685670: Q1.3(G) R163.2
N22685686: LD5.2(ANODE) R162.1
N24650378: R128.1 R130.2 U30.4(EN)

Not connected (* = marked no-connect by the designer): D1 2(NC)*; D2 2(NC)*; J15 A2(TX1+)* A3(TX1-)* A8(SBU1)* A10(RX2-)* A11(RX2+)* B2(TX2+)* B3(TX2-)* B8(SBU2)* B10(RX1-)* B11(RX1+)*; U4 8(A7)* 9(A8)* 12(B8)* 13(B7)*; U40 1(NC)*; U129 3(ID)* 5(NC)*

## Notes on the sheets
sheet 35
- USB1 - USB 2.0 TYPE-A
- D-Note :-
  Use power switch with OC indication
  Example TPS2051
  Connect to a SOC IO for OC detection
  Refer SK-AM62P-LP schematics
- 90E
- To Type- C connector
- To Type- A connector
- 90E
- D-Note:
  USBx_DRVVBUS  Pull-down is a DNI
  to implement wake-up from deep sleep.
  For Normal USB operation, there is an
  internal pull-down enabled during SoC reset.
  USBx_DRVVBUS external pulldown can
  be populated when wake-up from deep
  sleep is not  implemented.
- C
- C
- D-Note:
  VBUS divider and VBUS supply connection to processor USB0:1 interface:
  Connection of supply to USBx_VBUS pin is optional when USB interface
  is configured as Host
- Bypass option for L4
- Silk: TYPE-A
- 90E
- DLW21SZ900HQ2B
- D-Note:
  Refer to the USB VBUS Design
  Guidelines section of the
  processor-specific data sheet
  for implementing the VBUS voltage
- Bypass option for L4
- C
- CAD Note:
  Stack 0E resistor pads over
  the common mode choke pads
  Refer SK implementation
- D-Note:
  Provision to bypass the CMC using 0E (ohms) resistor provided
  for testing the USB interface performance
- C
sheet 36
- USB0 TYPE-C DRP
- D-Note:
  Refer to the SK/EVM user's guide for the recommended power adapters.
  Using the recommended adapter is recommended for proper functioning of SK/EVM
  Reference Document:
  EVM User's Guide : https://www.ti.com/lit/pdf/SPRUJ40
  Reference section : Power Requirement
- D-Note:
  Provide provision to bypass the CMC using
  0E (ohms) resistor for performance testing.
- Silk: TYPE-C DRP
- Bypass option for L7
- C
- C
- 90E
- DLW21SZ900HQ2B
- Bypass option for L7
- C
- POWER INDICATION LED: VBUS_TYPEC2
- C
- C
- CAD Note:
  Stack 0E resistor pads over
  the common mode choke pads
  Refer SK implementation
- V
- USER TEST LEDS
- POWER RAIL LEDS
- V
- V
- SoC GPIO
- V
- IO EXP GPIO
- V
- VBE = 0.85V
  Ic = 20mA
  Ib = 0.2mA
sheet 37
- SoC UART1 FET SWITCH & BUFFER
- D-Note:
  Add a pulldown for the clock input
  Add parallel pull for the SPI interface
  data signals and CS0
- OEn
- SEL
- INPUT/OUTPUT
- An
- L
- L
- An=nB1
- SOC - USER EXPANSION
           CONNECTOR
- L
- H(DEFAULT)
- An=nB2
- SOC - FT4232
- SoC_MAIN_UART1_RXD
- SoC_MAIN_UART1_CTS
- SoC_MAIN_UART1_TXD
- SoC_MAIN_UART1_RTS
- 2DIR=H : 2A ->2B
  1DIR=L : 1B ->1A
- (VCCA < OR = VCCB)
